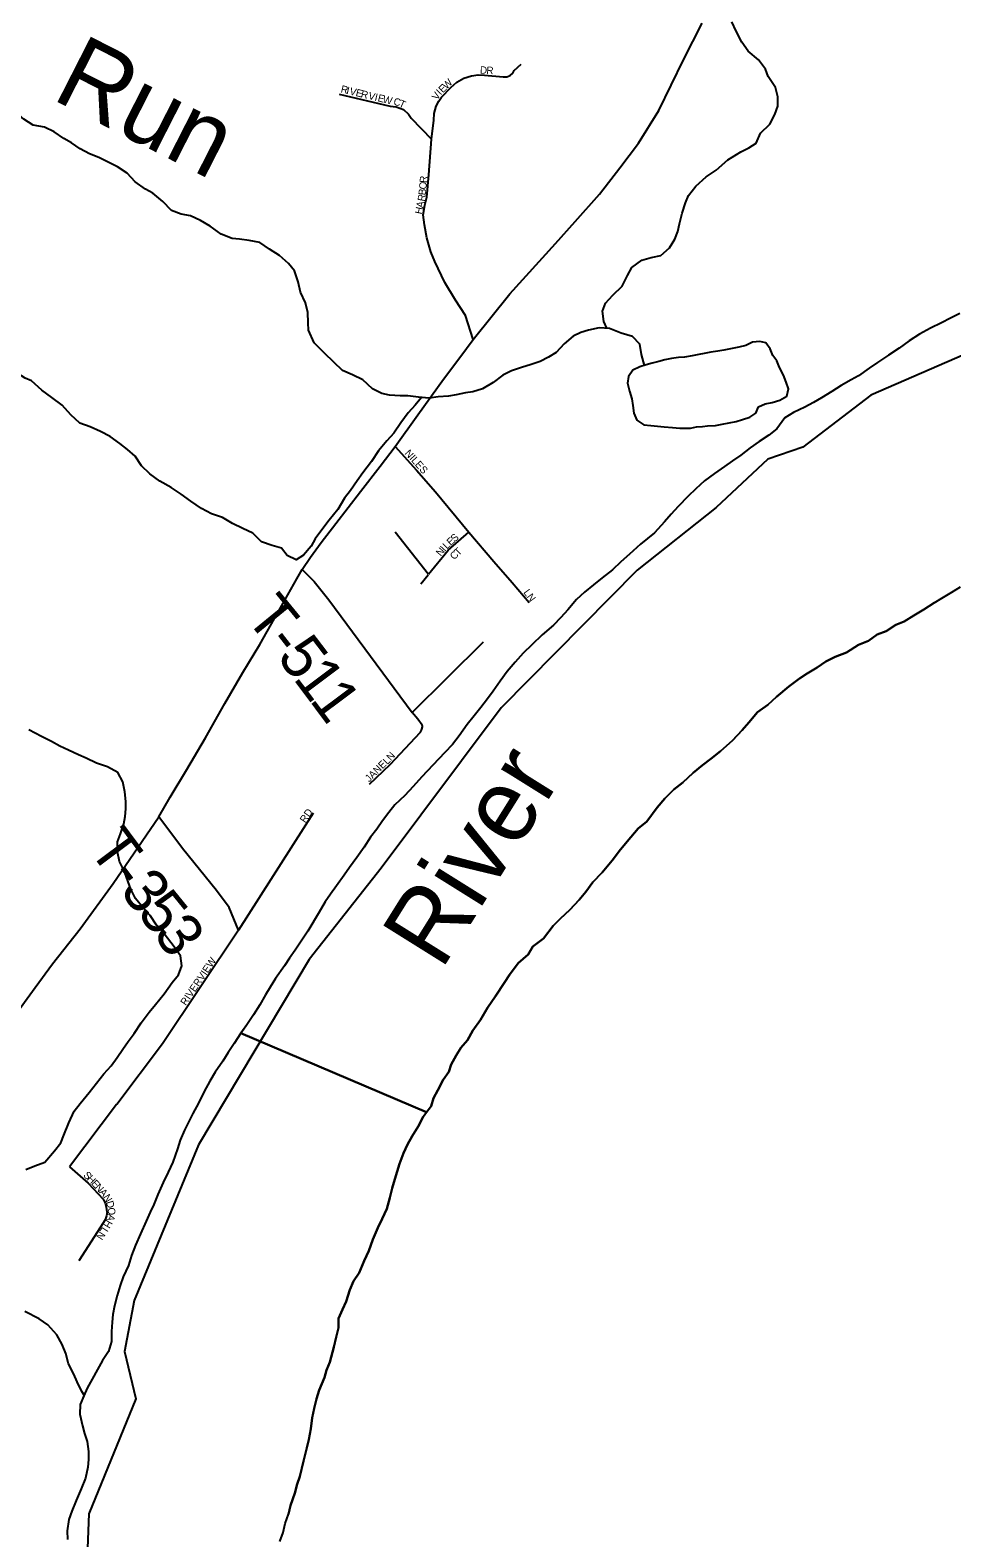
# Model space of a CAD drawing. Extents: x 1624196 to 2029251, y 146837 to 440034.
# Drawn here: x 1790059 to 1796343, y 239129 to 249407 of the extents above; entities that cross this region are included whole.
import ezdxf

# ---------------------------------------------------------------- set-up
doc = ezdxf.new("R2010")
doc.units = 0
for name, color, linetype in [('GM_X_County', 7, 'Continuous'), ('GM_X_Major_River', 7, 'Continuous'), ('GM_X_Major_River_Text', 7, 'Continuous'), ('GM_X_Minor_Lake', 7, 'Continuous'), ('GM_X_Minor_River', 7, 'Continuous'), ('GM_X_Minor_River_Text', 7, 'Continuous'), ('GM_X_Township', 7, 'Continuous'), ('GM_X_Township_Road', 7, 'Continuous'), ('GM_X_Township_Road_Text', 7, 'Continuous'), ('GM_X_Township_Subdivision', 7, 'Continuous'), ('GM_X_Township_Subdivision_Text', 7, 'Continuous'), ('GM_X_US_Route', 7, 'Continuous')]:
    doc.layers.add(name, color=color, linetype=linetype)

msp = doc.modelspace()

# ---------------------------------------------------------------- linework, layer by layer
at = {"layer": 'GM_X_County'}
msp.add_lwpolyline([(1802205, 248852), (1801771, 248582), (1801220, 248425), (1800376, 248227), (1798885, 247828), (1798571, 247796), (1797873, 247628), (1797463, 247527), (1796946, 247422), (1795791, 246920), (1795327, 246564), (1795089, 246483), (1794736, 246153), (1794197, 245725), (1793270, 244787), (1792451, 243695), (1791962, 243071), (1791207, 241809), (1790767, 240747), (1790703, 240400), (1790780, 240078), (1790458, 239293), (1790433, 238650)], dxfattribs=at)
at = {"layer": 'GM_X_Major_River'}
for p, q in [((1792761, 242031), (1791496, 242569)), ((1791496, 242569), (1792761, 242031))]:
    msp.add_line(p, q, dxfattribs=at)
for points in [[(1796397, 247476), (1796333, 247443), (1796273, 247413), (1796198, 247375), (1796122, 247334), (1796052, 247290), (1795983, 247240), (1795911, 247191), (1795835, 247141), (1795780, 247103), (1795706, 247050), (1795656, 247024), (1795589, 246984), (1795525, 246944), (1795453, 246901), (1795400, 246869), (1795340, 246837), (1795262, 246800)], [(1795262, 246800), (1795204, 246764), (1795149, 246690), (1795095, 246646), (1795030, 246602), (1794968, 246561), (1794904, 246509), (1794847, 246471), (1794793, 246433), (1794725, 246386), (1794656, 246334), (1794598, 246280), (1794544, 246230), (1794477, 246161), (1794429, 246107), (1794384, 246055), (1794316, 245981), (1794219, 245903), (1794145, 245834), (1794086, 245782), (1794030, 245728), (1793959, 245674), (1793899, 245627), (1793839, 245577), (1793784, 245527), (1793724, 245455), (1793677, 245403), (1793627, 245352), (1793550, 245284), (1793478, 245218), (1793421, 245160), (1793365, 245098), (1793310, 245035), (1793262, 244969), (1793215, 244901), (1793177, 244849), (1793131, 244789), (1793086, 244733), (1793038, 244673), (1792983, 244597), (1792939, 244537), (1792886, 244482), (1792804, 244396), (1792729, 244318), (1792671, 244252), (1792614, 244190), (1792546, 244127), (1792503, 244073), (1792461, 244017), (1792423, 243961), (1792380, 243905), (1792336, 243837), (1792287, 243767), (1792237, 243699), (1792200, 243647), (1792148, 243574), (1792107, 243518), (1792071, 243464), (1792030, 243394), (1791951, 243264), (1791866, 243136), (1791826, 243080), (1791792, 243028), (1791731, 242942), (1791695, 242884), (1791664, 242832), (1791624, 242764), (1791581, 242695), (1791537, 242627), (1791500, 242575), (1791450, 242499), (1791409, 242437), (1791373, 242379), (1791320, 242303), (1791284, 242243), (1791245, 242171), (1791207, 242093), (1791168, 242021), (1791140, 241967), (1791110, 241909), (1791081, 241841), (1791063, 241781), (1791032, 241691), (1791000, 241623), (1790965, 241551), (1790930, 241469), (1790902, 241401), (1790876, 241349), (1790849, 241289), (1790811, 241201), (1790778, 241125), (1790749, 241055), (1790729, 240985), (1790692, 240909), (1790672, 240849), (1790652, 240781), (1790633, 240711), (1790623, 240653), (1790618, 240600), (1790614, 240536), (1790613, 240468)], [(1795262, 246800), (1795204, 246764), (1795149, 246690), (1795095, 246646), (1795030, 246602), (1794968, 246561), (1794904, 246509), (1794847, 246471), (1794793, 246433), (1794725, 246386), (1794656, 246334), (1794598, 246280), (1794544, 246230), (1794477, 246161), (1794429, 246107), (1794384, 246055), (1794316, 245981), (1794219, 245903), (1794145, 245834), (1794086, 245782), (1794030, 245728), (1793959, 245674), (1793899, 245627), (1793839, 245577), (1793784, 245527), (1793724, 245455), (1793677, 245403), (1793627, 245352), (1793550, 245284), (1793478, 245218), (1793421, 245160), (1793365, 245098), (1793310, 245035), (1793262, 244969), (1793215, 244901), (1793177, 244849), (1793131, 244789), (1793086, 244733), (1793038, 244673), (1792983, 244597), (1792939, 244537), (1792886, 244482), (1792804, 244396), (1792729, 244318), (1792671, 244252), (1792614, 244190), (1792546, 244127), (1792503, 244073), (1792461, 244017), (1792423, 243961), (1792380, 243905), (1792336, 243837), (1792287, 243767), (1792237, 243699), (1792200, 243647), (1792148, 243574), (1792107, 243518), (1792071, 243464), (1792030, 243394), (1791951, 243264), (1791866, 243136), (1791826, 243080), (1791792, 243028), (1791731, 242942), (1791695, 242884), (1791664, 242832), (1791624, 242764), (1791581, 242695), (1791537, 242627), (1791496, 242569)], [(1796221, 245503), (1796274, 245535), (1796342, 245575), (1796402, 245613)], [(1796221, 245503), (1796151, 245458), (1796083, 245418), (1796018, 245376), (1795960, 245353), (1795894, 245309), (1795834, 245287), (1795775, 245245), (1795707, 245216), (1795625, 245164), (1795548, 245135), (1795484, 245103), (1795424, 245063), (1795357, 245021), (1795305, 244988), (1795231, 244934), (1795148, 244862), (1795088, 244809), (1795017, 244759), (1794959, 244687), (1794913, 244635), (1794846, 244565), (1794765, 244492), (1794699, 244440), (1794643, 244396), (1794578, 244344), (1794508, 244279), (1794447, 244231), (1794385, 244169), (1794333, 244109), (1794262, 244013), (1794203, 243966), (1794153, 243906), (1794084, 243822), (1794026, 243746), (1793959, 243664), (1793895, 243598), (1793848, 243533), (1793802, 243479), (1793737, 243411), (1793675, 243351), (1793625, 243301), (1793558, 243215), (1793486, 243160), (1793453, 243106), (1793385, 243048), (1793326, 242968), (1793292, 242916), (1793231, 242822), (1793176, 242742), (1793130, 242661), (1793077, 242589), (1793041, 242521), (1792994, 242469), (1792962, 242417), (1792930, 242357), (1792913, 242307), (1792875, 242251), (1792838, 242181), (1792808, 242127), (1792792, 242073), (1792737, 241999), (1792703, 241933), (1792662, 241867), (1792632, 241811), (1792605, 241751), (1792577, 241679), (1792546, 241575), (1792526, 241513), (1792511, 241447), (1792491, 241373), (1792458, 241303), (1792430, 241243), (1792395, 241163), (1792367, 241087), (1792336, 241017), (1792301, 240935), (1792263, 240879), (1792239, 240821), (1792214, 240741), (1792188, 240687), (1792161, 240625), (1792161, 240560), (1792146, 240498), (1792128, 240430), (1792101, 240326), (1792079, 240272), (1792066, 240222), (1792030, 240136), (1792011, 240078), (1791995, 240012), (1791982, 239948), (1791972, 239872), (1791959, 239799), (1791945, 239743), (1791922, 239651), (1791898, 239547), (1791879, 239495), (1791863, 239435), (1791834, 239351), (1791820, 239291)], [(1792761, 242031), (1792792, 242073), (1792808, 242127), (1792838, 242181), (1792875, 242251), (1792913, 242307), (1792930, 242357), (1792962, 242417), (1792994, 242469), (1793041, 242521), (1793077, 242589), (1793130, 242661), (1793176, 242742), (1793231, 242822), (1793292, 242916), (1793326, 242968), (1793385, 243048), (1793453, 243106), (1793486, 243160), (1793558, 243215), (1793625, 243301), (1793675, 243351), (1793737, 243411), (1793802, 243479), (1793848, 243533), (1793895, 243598), (1793959, 243664), (1794026, 243746), (1794084, 243822), (1794153, 243906), (1794203, 243966), (1794262, 244013), (1794333, 244109), (1794385, 244169), (1794447, 244231), (1794508, 244279), (1794578, 244344), (1794643, 244396), (1794699, 244440), (1794765, 244492), (1794846, 244565), (1794913, 244635), (1794959, 244687), (1795017, 244759), (1795088, 244809), (1795148, 244862), (1795231, 244934), (1795305, 244988), (1795357, 245021), (1795424, 245063), (1795484, 245103), (1795548, 245135), (1795625, 245164), (1795707, 245216), (1795775, 245245), (1795834, 245287), (1795894, 245309), (1795960, 245353), (1796018, 245376), (1796083, 245418), (1796151, 245458), (1796221, 245503)], [(1791496, 242569), (1791450, 242499), (1791409, 242437), (1791373, 242379), (1791320, 242303), (1791284, 242243), (1791245, 242171), (1791207, 242093), (1791168, 242021), (1791140, 241967), (1791110, 241909), (1791081, 241841), (1791063, 241781), (1791032, 241691), (1791000, 241623), (1790965, 241551), (1790930, 241469), (1790902, 241401), (1790876, 241349), (1790849, 241289), (1790811, 241201), (1790778, 241125), (1790749, 241055), (1790729, 240985), (1790692, 240909), (1790672, 240849), (1790652, 240781), (1790633, 240711), (1790623, 240653), (1790618, 240600), (1790614, 240536), (1790613, 240468)], [(1791820, 239291), (1791834, 239351), (1791863, 239435), (1791879, 239495), (1791898, 239547), (1791922, 239651), (1791945, 239743), (1791959, 239799), (1791972, 239872), (1791982, 239948), (1791995, 240012), (1792011, 240078), (1792030, 240136), (1792066, 240222), (1792079, 240272), (1792101, 240326), (1792128, 240430), (1792146, 240498), (1792161, 240560), (1792161, 240625), (1792188, 240687), (1792214, 240741), (1792239, 240821), (1792263, 240879), (1792301, 240935), (1792336, 241017), (1792367, 241087), (1792395, 241163), (1792430, 241243), (1792458, 241303), (1792491, 241373), (1792511, 241447), (1792526, 241513), (1792546, 241575), (1792577, 241679), (1792605, 241751), (1792632, 241811), (1792662, 241867), (1792703, 241933), (1792737, 241999), (1792761, 242031)], [(1790613, 240468), (1790593, 240400), (1790552, 240338), (1790518, 240276), (1790481, 240212), (1790447, 240150), (1790425, 240098), (1790400, 240038), (1790398, 239972), (1790415, 239894), (1790429, 239841), (1790447, 239787), (1790456, 239719), (1790456, 239663), (1790453, 239612), (1790435, 239536), (1790406, 239464), (1790372, 239384), (1790343, 239312), (1790323, 239254), (1790310, 239178), (1790314, 239118)], [(1791760, 239105), (1791783, 239165), (1791797, 239227), (1791820, 239291)]]:
    msp.add_lwpolyline(points, dxfattribs=at)
at = {"layer": 'GM_X_Minor_Lake'}
for points in [[(1794992, 246787), (1795006, 246796), (1795024, 246840), (1795070, 246860), (1795118, 246869), (1795169, 246885), (1795217, 246911), (1795229, 246961), (1795212, 247007), (1795194, 247056), (1795168, 247108), (1795150, 247152), (1795121, 247190), (1795103, 247235), (1795075, 247275), (1795033, 247285), (1794983, 247280), (1794939, 247258), (1794891, 247246), (1794845, 247236), (1794789, 247225), (1794746, 247219), (1794700, 247213), (1794572, 247188)], [(1794572, 247188), (1794520, 247178), (1794480, 247176), (1794432, 247169), (1794386, 247159), (1794344, 247149), (1794299, 247137), (1794259, 247126), (1794215, 247112), (1794167, 247090), (1794137, 247046), (1794132, 247000), (1794146, 246946), (1794160, 246893), (1794167, 246849), (1794175, 246797), (1794195, 246749), (1794243, 246716), (1794291, 246712), (1794335, 246708), (1794381, 246703), (1794439, 246699), (1794487, 246695), (1794517, 246693), (1794561, 246694), (1794601, 246702), (1794643, 246706), (1794677, 246710), (1794731, 246713), (1794777, 246721), (1794825, 246731), (1794871, 246740), (1794916, 246754), (1794966, 246770), (1794992, 246787)]]:
    msp.add_lwpolyline(points, dxfattribs=at)
at = {"layer": 'GM_X_Minor_River'}
for points in [[(1793991, 247375), (1793971, 247420), (1793960, 247491), (1793982, 247545), (1794032, 247601), (1794095, 247663), (1794131, 247735), (1794160, 247789), (1794230, 247840), (1794292, 247858), (1794358, 247870), (1794417, 247923), (1794453, 247983), (1794474, 248034), (1794486, 248086), (1794503, 248160), (1794527, 248230), (1794547, 248280), (1794596, 248344), (1794668, 248408), (1794735, 248453), (1794815, 248523), (1794904, 248577), (1794958, 248605), (1795008, 248636), (1795037, 248704), (1795101, 248766), (1795136, 248832), (1795156, 248888), (1795157, 248953), (1795141, 249017), (1795091, 249091), (1795072, 249142), (1795024, 249204), (1794954, 249265), (1794911, 249325), (1794871, 249400), (1794842, 249464)], [(1790079, 248759), (1790015, 248800), (1789955, 248852), (1789905, 248872), (1789839, 248895), (1789769, 248951), (1789713, 248998), (1789651, 249058), (1789601, 249123), (1789539, 249187), (1789466, 249244), (1789428, 249296), (1789366, 249361), (1789294, 249423)], [(1794246, 247122), (1794226, 247196), (1794216, 247266), (1794165, 247319), (1794087, 247341), (1794009, 247374), (1793937, 247379), (1793865, 247361), (1793812, 247347), (1793760, 247321), (1793700, 247268), (1793645, 247210), (1793593, 247178), (1793535, 247148), (1793467, 247125), (1793416, 247109), (1793340, 247085), (1793282, 247056), (1793216, 247006), (1793143, 246962), (1793077, 246942), (1793027, 246935), (1792963, 246921), (1792911, 246911), (1792841, 246908), (1792778, 246898), (1792706, 246905), (1792634, 246915), (1792582, 246915), (1792508, 246920), (1792456, 246930), (1792393, 246963), (1792327, 247023), (1792257, 247058), (1792189, 247086), (1792129, 247143), (1792066, 247206), (1791996, 247276), (1791957, 247361), (1791955, 247413), (1791952, 247483), (1791936, 247548), (1791902, 247622), (1791885, 247692), (1791861, 247767), (1791820, 247817), (1791758, 247870), (1791690, 247914), (1791624, 247959), (1791552, 247974), (1791486, 247982), (1791436, 247988), (1791361, 248017), (1791285, 248072), (1791219, 248110), (1791151, 248141), (1791089, 248153), (1791023, 248178), (1790964, 248238), (1790896, 248295), (1790844, 248323), (1790774, 248374), (1790721, 248432), (1790655, 248475), (1790585, 248510), (1790527, 248538), (1790463, 248564), (1790400, 248599), (1790340, 248640), (1790288, 248668), (1790222, 248715), (1790156, 248745), (1790079, 248759)], [(1790067, 247017), (1790025, 247035), (1789957, 247079), (1789887, 247122), (1789824, 247187), (1789774, 247215), (1789716, 247241), (1789662, 247274), (1789598, 247318), (1789526, 247377), (1789454, 247405), (1789386, 247426), (1789261, 247470)], [(1792726, 246903), (1792684, 246851), (1792636, 246799), (1792585, 246731), (1792537, 246661), (1792490, 246607), (1792434, 246539), (1792387, 246467), (1792327, 246389), (1792288, 246335), (1792242, 246269), (1792201, 246217), (1792157, 246139), (1792098, 246067), (1792048, 246002), (1792001, 245940), (1791975, 245890), (1791923, 245828), (1791872, 245796), (1791812, 245826), (1791773, 245877), (1791709, 245893), (1791637, 245918), (1791577, 245978), (1791509, 246009), (1791439, 246043), (1791370, 246084), (1791294, 246109), (1791226, 246147), (1791154, 246196), (1791088, 246244), (1791019, 246289), (1790943, 246332), (1790875, 246382), (1790818, 246437), (1790774, 246503), (1790722, 246548), (1790670, 246590), (1790605, 246637), (1790539, 246671), (1790467, 246702), (1790397, 246728), (1790335, 246785), (1790276, 246850), (1790206, 246904), (1790138, 246953), (1790067, 247017)], [(1790030, 241640), (1790091, 241665), (1790158, 241691), (1790224, 241768), (1790267, 241822), (1790289, 241874), (1790323, 241958), (1790358, 242039), (1790400, 242090), (1790461, 242166), (1790511, 242230), (1790562, 242292), (1790610, 242346), (1790653, 242404), (1790691, 242460), (1790726, 242514), (1790768, 242568), (1790816, 242640), (1790869, 242712), (1790913, 242766), (1790972, 242839), (1791026, 242915), (1791069, 242967), (1791093, 243029), (1791084, 243098), (1791034, 243168), (1790979, 243237), (1790919, 243307), (1790877, 243372), (1790830, 243424), (1790778, 243487), (1790744, 243551), (1790727, 243602), (1790701, 243672), (1790668, 243740), (1790654, 243807), (1790654, 243875), (1790675, 243929), (1790697, 243997), (1790706, 244047), (1790712, 244099), (1790710, 244150), (1790705, 244214), (1790691, 244282), (1790656, 244347), (1790586, 244385), (1790512, 244410), (1790440, 244444), (1790388, 244467), (1790320, 244499), (1790262, 244526), (1790204, 244558), (1790137, 244591), (1790050, 244637)], [(1790426, 240101), (1790410, 240126), (1790380, 240194), (1790356, 240245), (1790321, 240315), (1790301, 240387), (1790278, 240448), (1790240, 240514), (1790180, 240581), (1790119, 240623), (1790023, 240673)]]:
    msp.add_lwpolyline(points, dxfattribs=at)
at = {"layer": 'GM_X_Township'}
msp.add_lwpolyline([(1802205, 248852), (1801771, 248582), (1801220, 248425), (1800376, 248227), (1798885, 247828), (1798571, 247796), (1797873, 247628), (1797463, 247527), (1796946, 247422), (1795791, 246920), (1795327, 246564), (1795089, 246483), (1794736, 246153), (1794197, 245725), (1793270, 244787), (1792451, 243695), (1791962, 243071), (1791207, 241809), (1790767, 240747), (1790703, 240400), (1790780, 240078), (1790458, 239293), (1790433, 238650)], dxfattribs=at)
at = {"layer": 'GM_X_Township_Road'}
for points in [[(1791914, 245731), (1791996, 245648), (1792095, 245523), (1792663, 244756), (1793149, 245238)], [(1791478, 243273), (1791416, 243427), (1791329, 243542), (1791098, 243828), (1790936, 244044)]]:
    msp.add_lwpolyline(points, dxfattribs=at)
at = {"layer": 'GM_X_Township_Subdivision'}
for points in [[(1793078, 247298), (1793026, 247462), (1792958, 247566), (1792885, 247687), (1792818, 247830), (1792791, 247897), (1792763, 247992), (1792748, 248080), (1792739, 248148), (1792750, 248213), (1792763, 248269), (1792776, 248421), (1792795, 248664), (1792811, 248794), (1792814, 248840), (1792827, 248889), (1792845, 248923), (1792862, 248950), (1792927, 249017), (1792968, 249053), (1793015, 249080), (1793067, 249096), (1793114, 249102), (1793156, 249101), (1793283, 249090), (1793287, 249089), (1793297, 249089), (1793308, 249090), (1793320, 249094), (1793331, 249099), (1793349, 249114), (1793359, 249132), (1793407, 249175)], [(1792166, 248970), (1792514, 248890), (1792554, 248885), (1792603, 248866), (1792638, 248834), (1792657, 248807), (1792795, 248664)], [(1792548, 246569), (1792692, 246408), (1792822, 246260), (1793050, 245984), (1793221, 245785), (1793344, 245642), (1793461, 245505)], [(1792548, 245988), (1792775, 245698)], [(1792775, 245698), (1792908, 245862), (1793050, 245984)], [(1792722, 245632), (1792773, 245695)], [(1792373, 244267), (1792513, 244402), (1792720, 244622), (1792727, 244635), (1792729, 244643), (1792733, 244658), (1792734, 244664), (1792732, 244669), (1792701, 244710), (1792663, 244756)], [(1791989, 244069), (1791478, 243273), (1790960, 242498), (1790649, 242084), (1790648, 242083)], [(1790648, 242083), (1790328, 241658)], [(1790328, 241658), (1790454, 241548), (1790557, 241439), (1790571, 241412), (1790577, 241383), (1790581, 241352), (1790583, 241350), (1790580, 241324), (1790569, 241298), (1790538, 241248), (1790391, 241017)]]:
    msp.add_lwpolyline(points, dxfattribs=at)
at = {"layer": 'GM_X_US_Route'}
for points in [[(1793774, 248102), (1793941, 248289), (1794078, 248468), (1794206, 248637), (1794344, 248859), (1794514, 249204), (1794641, 249455)], [(1790936, 244044), (1791014, 244179), (1791126, 244367), (1791255, 244584), (1791386, 244816), (1791508, 245029), (1791624, 245220), (1791775, 245485), (1791877, 245666), (1791914, 245731), (1791969, 245815), (1792042, 245915), (1792142, 246045), (1792312, 246262), (1792445, 246436), (1792548, 246569), (1792702, 246784), (1792876, 247029), (1792988, 247176), (1793078, 247298), (1793330, 247610), (1793640, 247952), (1793774, 248102)], [(1789325, 241720), (1789359, 241778), (1789475, 241977), (1789565, 242139), (1789638, 242261), (1789690, 242341), (1789936, 242665), (1790092, 242880), (1790210, 243042), (1790400, 243280), (1790625, 243591), (1790936, 244044)]]:
    msp.add_lwpolyline(points, dxfattribs=at)

# ---------------------------------------------------------------- texts
at = {"layer": 'GM_X_Major_River_Text'}
msp.add_text('River', height=500.1, rotation=58.0031, dxfattribs=at).set_placement((1792862, 242992))
at = {"layer": 'GM_X_Minor_River_Text'}
msp.add_text('Run', height=500, rotation=332.9936, dxfattribs=at).set_placement((1790196, 248942))
at = {"layer": 'GM_X_Township_Road_Text'}
for s, rotation, p in [('T', 309.2736, (1791519, 245403)), ('-', 307.7918, (1791660, 245231)), ('5', 307.2935, (1791735, 245134)), ('1', 306.9016, (1791847, 244988)), ('1', 306.7976, (1791958, 244840)), ('T', 306.6569, (1790450, 243824)), ('-', 307.0914, (1790586, 243642)), ('3', 308.2307, (1790664, 243538)), ('5', 309.1023, (1790781, 243389)), ('3', 303.6944, (1790893, 243252))]:
    msp.add_text(s, height=300, rotation=rotation, dxfattribs=at).set_placement(p)
at = {"layer": 'GM_X_Township_Subdivision_Text'}
for s, rotation, p in [('D', 358.3603, (1793125, 249111)), ('R', 356.0389, (1793168, 249110)), ('R', 346.3819, (1792173, 248984)), ('E', 45.7726, (1792873, 248976)), ('W', 42.8833, (1792897, 249001)), ('I', 346.3763, (1792211, 248974)), ('V', 346.3878, (1792233, 248969)), ('E', 346.3898, (1792275, 248959)), ('R', 346.3819, (1792310, 248950)), ('V', 346.3813, (1792361, 248938)), ('I', 346.3878, (1792404, 248928)), ('E', 346.3746, (1792425, 248923)), ('W', 346.7862, (1792460, 248914)), ('C', 345.6457, (1792532, 248899)), ('T', 336.0264, (1792568, 248889)), ('V', 56.2917, (1792835, 248926)), ('I', 47.1794, (1792858, 248961)), ('B', 84.135, (1792755, 248280)), ('O', 84.9697, (1792759, 248320)), ('R', 84.9419, (1792763, 248364)), ('A', 77.9785, (1792738, 248192)), ('R', 79.5121, (1792748, 248237)), ('H', 77.9999, (1792729, 248149)), ('NILES', 311.8796, (1792609, 246521)), ('E', 41.7821, (1792925, 245890)), ('S', 41.646, (1792952, 245914)), ('N', 49.9985, (1792858, 245817)), ('I', 48.2938, (1792886, 245850)), ('L', 43.9759, (1792900, 245866)), ('C', 47.1643, (1792951, 245793)), ('T', 43.0577, (1792978, 245821)), ('LN', 306.2589, (1793419, 245574)), ('JANE', 44.9977, (1792371, 244278)), ('L', 46.3331, (1792494, 244397)), ('N', 47.4015, (1792519, 244423)), ('RD', 55.4981, (1791934, 243999)), ('RIVERVIEW', 55.9037, (1791120, 242754)), ('S', 314.9227, (1790417, 241598)), ('H', 314.0649, (1790442, 241573)), ('E', 312.6523, (1790472, 241542)), ('N', 312.1781, (1790496, 241516)), ('A', 312.1809, (1790526, 241483)), ('N', 301.0706, (1790554, 241453)), ('D', 287.1284, (1790575, 241418)), ('A', 254.0126, (1790592, 241340)), ('O', 275.3191, (1790587, 241379)), ('L', 237.8556, (1790552, 241252)), ('H', 239.3361, (1790581, 241301)), ('N', 237.8785, (1790533, 241222))]:
    msp.add_text(s, height=50, rotation=rotation, dxfattribs=at).set_placement(p)

doc.saveas('drawing.dxf')
